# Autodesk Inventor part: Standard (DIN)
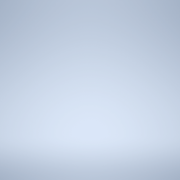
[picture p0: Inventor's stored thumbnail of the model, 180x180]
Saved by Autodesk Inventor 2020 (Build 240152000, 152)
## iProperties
Created: 2019-02
Part Number: Standard (DIN)
Material: Ogólny
Document SubType Name: Modeling
Density: 1 g/cm^3
Appearance: Domyślna
Designer: F.Stasiak
Manager: www.cadconsulting.pl
Company: Fabian Stasiak CAD Consulting
Subject: Zbiór ćwiczeń. Autodesk Inventor 2020. Kurs podstawowy
Author: F.Stasiak
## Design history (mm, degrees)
